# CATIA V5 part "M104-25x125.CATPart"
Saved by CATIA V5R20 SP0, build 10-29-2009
Part number: M104-25x125
Source: Unknown
Bounding box of the stored display mesh (mm): x -12.497 to 12.497, y -12.358 to 12.358, z 0 to 125
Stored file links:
  C:\Users\Utente\Desktop\IO LAVORO\3D X SITO CF\X SITO\M104\M104-25x125.CATPart
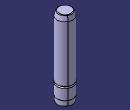
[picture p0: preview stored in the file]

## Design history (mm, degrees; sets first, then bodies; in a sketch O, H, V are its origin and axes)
Body1 (main body)
  Solid1 "PartBody": solid without history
